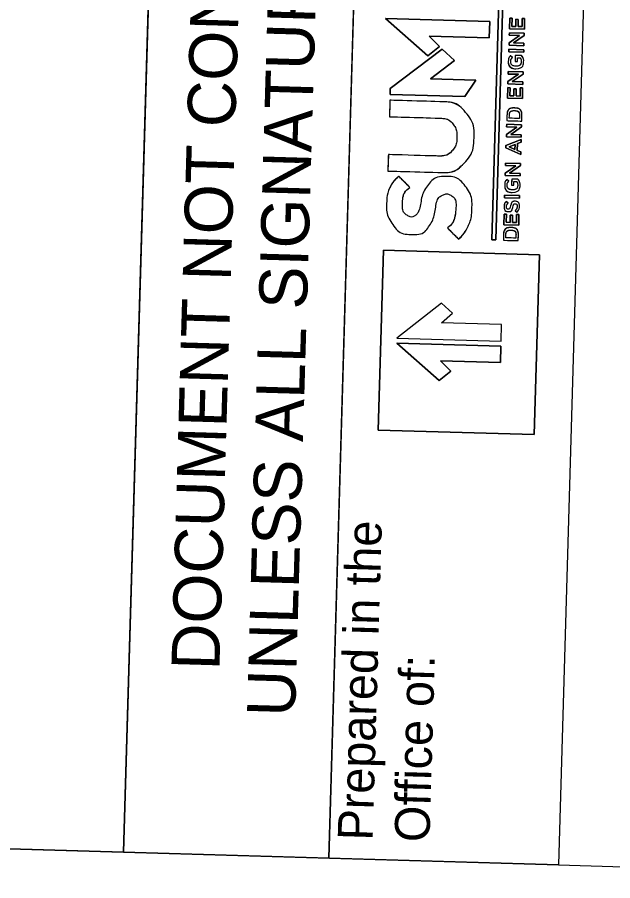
# Model space of a CAD drawing. Extents: x 2097000 to 2098148, y 684979 to 687012.
# Drawn here: x 2097192.5 to 2097260.6, y 686617.1 to 686715.9 of the extents above; entities that cross this region are included whole.
import ezdxf

# ---------------------------------------------------------------- set-up
doc = ezdxf.new("R2010")
doc.units = 0
for name, color, linetype in [('Sheet Block Title CELL', 7, 'Continuous'), ('Sheet Layout Plan Border', 7, 'Continuous'), ('Sheet Profile CELL', 7, 'Continuous'), ('Sheet Sticker Exception Certification CELL', 7, 'Continuous')]:
    doc.layers.add(name, color=color, linetype=linetype)

msp = doc.modelspace()

# ---------------------------------------------------------------- linework, layer by layer
at = {"layer": 'Sheet Block Title CELL'}
for p, q in [((2097249.112, 686711.281), (2097248.892, 686711.47)), ((2097249.497, 686709.984), (2097249.502, 686709.984)), ((2097249.506, 686710.284), (2097249.501, 686710.284)), ((2097249.367, 686705.496), (2097249.362, 686705.496)), ((2097249.358, 686705.195), (2097249.363, 686705.195)), ((2097237.381, 686696.412), (2097236.115, 686697.7)), ((2097248.701, 686697.137), (2097248.48, 686697.325)), ((2097249.086, 686695.839), (2097249.091, 686695.839)), ((2097249.095, 686696.139), (2097249.09, 686696.14)), ((2097248.616, 686694.646), (2097248.395, 686694.807)), ((2097249.423, 686694.825), (2097249.418, 686694.826)), ((2097249.439, 686694.538), (2097249.444, 686694.538)), ((2097248.627, 686693.937), (2097248.622, 686693.937)), ((2097248.641, 686693.65), (2097248.646, 686693.65)), ((2097249.413, 686693.735), (2097249.622, 686693.557)), ((2097241.682, 686691.784), (2097242.949, 686690.496)), ((2097248.969, 686691.824), (2097248.964, 686691.824)), ((2097248.96, 686691.523), (2097248.965, 686691.523))]:
    msp.add_line(p, q, dxfattribs=at)
for points in [[(2097228.129, 686619.71), (2097233.943, 686819.684), (2097260.188, 686818.921), (2097254.374, 686618.947)], [(2097233.761, 686668.67), (2097234.358, 686689.219), (2097252.194, 686688.7), (2097251.596, 686668.152)], [(2097235.893, 686679.192), (2097247.818, 686678.845), (2097247.873, 686680.724), (2097240.994, 686680.924), (2097242.26, 686682.051), (2097240.985, 686683.183)]]:
    msp.add_lwpolyline(points, close=True, dxfattribs=at)
for points in [[(2097248.533, 686735.929), (2097247.21, 686690.408), (2097246.758, 686690.422), (2097248.081, 686735.942), (2097248.533, 686735.929)], [(2097248.081, 686735.942), (2097246.758, 686690.422), (2097247.21, 686690.408), (2097248.533, 686735.929), (2097248.081, 686735.942)], [(2097234.598, 686715.748), (2097246.523, 686715.401), (2097246.468, 686713.523), (2097239.59, 686713.723), (2097240.787, 686712.523), (2097239.449, 686711.468), (2097234.598, 686715.748)], [(2097239.449, 686711.468), (2097240.787, 686712.523), (2097239.59, 686713.723), (2097246.468, 686713.523), (2097246.523, 686715.401), (2097234.598, 686715.748), (2097239.449, 686711.468)], [(2097248.779, 686714.553), (2097248.815, 686715.761), (2097249.082, 686715.753), (2097249.055, 686714.831), (2097249.497, 686714.819), (2097249.52, 686715.636), (2097249.788, 686715.628), (2097249.764, 686714.811), (2097250.22, 686714.797), (2097250.247, 686715.731), (2097250.514, 686715.724), (2097250.479, 686714.503), (2097248.779, 686714.553)], [(2097250.479, 686714.503), (2097250.514, 686715.724), (2097250.247, 686715.731), (2097250.22, 686714.797), (2097249.764, 686714.811), (2097249.788, 686715.628), (2097249.52, 686715.636), (2097249.497, 686714.819), (2097249.055, 686714.831), (2097249.082, 686715.753), (2097248.815, 686715.761), (2097248.779, 686714.553), (2097250.479, 686714.503)], [(2097248.725, 686712.667), (2097248.732, 686712.933), (2097249.933, 686713.772), (2097248.758, 686713.806), (2097248.766, 686714.088), (2097250.465, 686714.038), (2097250.458, 686713.798), (2097249.223, 686712.935), (2097250.432, 686712.9), (2097250.424, 686712.618), (2097248.725, 686712.667)], [(2097250.424, 686712.618), (2097250.432, 686712.9), (2097249.223, 686712.935), (2097250.458, 686713.798), (2097250.465, 686714.038), (2097248.766, 686714.088), (2097248.758, 686713.806), (2097249.933, 686713.772), (2097248.732, 686712.933), (2097248.725, 686712.667), (2097250.424, 686712.618)], [(2097235.141, 686707.717), (2097241.077, 686712.21), (2097242.502, 686710.937), (2097239.75, 686708.816), (2097244.914, 686708.665), (2097243.659, 686706.807), (2097235.121, 686707.055), (2097235.141, 686707.717)], [(2097235.121, 686707.055), (2097243.659, 686706.807), (2097244.914, 686708.665), (2097239.75, 686708.816), (2097242.502, 686710.937), (2097241.077, 686712.21), (2097235.141, 686707.717), (2097235.121, 686707.055)], [(2097248.703, 686711.922), (2097248.711, 686712.209), (2097250.411, 686712.159), (2097250.402, 686711.873), (2097248.703, 686711.922)], [(2097250.402, 686711.873), (2097250.411, 686712.159), (2097248.711, 686712.209), (2097248.703, 686711.922), (2097250.402, 686711.873)], [(2097250.156, 686711.491), (2097249.442, 686711.512), (2097249.422, 686710.818), (2097249.681, 686710.81), (2097249.694, 686711.227), (2097250.012, 686711.218)], [(2097248.596, 686708.242), (2097248.604, 686708.507), (2097249.804, 686709.346), (2097248.629, 686709.38), (2097248.637, 686709.662), (2097250.337, 686709.613), (2097250.33, 686709.373), (2097249.095, 686708.509), (2097250.304, 686708.474), (2097250.295, 686708.192), (2097248.596, 686708.242)], [(2097250.295, 686708.192), (2097250.304, 686708.474), (2097249.095, 686708.509), (2097250.33, 686709.373), (2097250.337, 686709.613), (2097248.637, 686709.662), (2097248.629, 686709.38), (2097249.804, 686709.346), (2097248.604, 686708.507), (2097248.596, 686708.242), (2097250.295, 686708.192)], [(2097248.549, 686706.612), (2097248.584, 686707.821), (2097248.851, 686707.813), (2097248.824, 686706.891), (2097249.266, 686706.878), (2097249.29, 686707.695), (2097249.557, 686707.687), (2097249.533, 686706.87), (2097249.989, 686706.857), (2097250.016, 686707.791), (2097250.283, 686707.783), (2097250.248, 686706.563), (2097248.549, 686706.612)], [(2097250.248, 686706.563), (2097250.283, 686707.783), (2097250.016, 686707.791), (2097249.989, 686706.857), (2097249.533, 686706.87), (2097249.557, 686707.687), (2097249.29, 686707.695), (2097249.266, 686706.878), (2097248.824, 686706.891), (2097248.851, 686707.813), (2097248.584, 686707.821), (2097248.549, 686706.612), (2097250.248, 686706.563)], [(2097241.253, 686706.202), (2097235.102, 686706.381), (2097235.047, 686704.502), (2097240.676, 686704.338)], [(2097248.492, 686704.654), (2097248.474, 686704.047), (2097250.173, 686703.997), (2097250.191, 686704.605)], [(2097249.919, 686704.613), (2097249.91, 686704.292), (2097248.754, 686704.325), (2097248.764, 686704.646)], [(2097248.421, 686702.208), (2097248.428, 686702.473), (2097249.629, 686703.312), (2097248.454, 686703.346), (2097248.462, 686703.628), (2097250.161, 686703.579), (2097250.154, 686703.339), (2097248.919, 686702.475), (2097250.128, 686702.44), (2097250.12, 686702.158), (2097248.421, 686702.208)], [(2097250.12, 686702.158), (2097250.128, 686702.44), (2097248.919, 686702.475), (2097250.154, 686703.339), (2097250.161, 686703.579), (2097248.462, 686703.628), (2097248.454, 686703.346), (2097249.629, 686703.312), (2097248.428, 686702.473), (2097248.421, 686702.208), (2097250.12, 686702.158)], [(2097248.372, 686700.946), (2097248.379, 686701.212), (2097250.112, 686701.879), (2097250.103, 686701.576), (2097249.688, 686701.423), (2097249.666, 686700.652), (2097250.071, 686700.473), (2097250.062, 686700.179), (2097248.372, 686700.946)], [(2097250.062, 686700.179), (2097250.071, 686700.473), (2097249.666, 686700.652), (2097249.688, 686701.423), (2097250.103, 686701.576), (2097250.112, 686701.879), (2097248.379, 686701.212), (2097248.372, 686700.946), (2097250.062, 686700.179)], [(2097249.42, 686701.326), (2097248.732, 686701.064), (2097249.404, 686700.765), (2097249.42, 686701.326)], [(2097249.404, 686700.765), (2097248.732, 686701.064), (2097249.42, 686701.326), (2097249.404, 686700.765)], [(2097240.55, 686700.003), (2097234.921, 686700.167), (2097234.867, 686698.288), (2097241.017, 686698.109)], [(2097248.292, 686697.784), (2097248.3, 686698.05), (2097249.5, 686698.889), (2097248.325, 686698.923), (2097248.333, 686699.205), (2097250.033, 686699.155), (2097250.026, 686698.915), (2097248.791, 686698.052), (2097250, 686698.017), (2097249.991, 686697.735), (2097248.292, 686697.784)], [(2097249.991, 686697.735), (2097250, 686698.017), (2097248.791, 686698.052), (2097250.026, 686698.915), (2097250.033, 686699.155), (2097248.333, 686699.205), (2097248.325, 686698.923), (2097249.5, 686698.889), (2097248.3, 686698.05), (2097248.292, 686697.784), (2097249.991, 686697.735)], [(2097249.744, 686697.346), (2097249.031, 686697.367), (2097249.011, 686696.673), (2097249.27, 686696.666), (2097249.282, 686697.083), (2097249.6, 686697.073)], [(2097248.218, 686695.238), (2097248.226, 686695.524), (2097249.926, 686695.475), (2097249.917, 686695.188), (2097248.218, 686695.238)], [(2097249.917, 686695.188), (2097249.926, 686695.475), (2097248.226, 686695.524), (2097248.218, 686695.238), (2097249.917, 686695.188)], [(2097248.128, 686692.148), (2097248.163, 686693.357), (2097248.43, 686693.349), (2097248.404, 686692.427), (2097248.845, 686692.414), (2097248.869, 686693.232), (2097249.136, 686693.224), (2097249.112, 686692.406), (2097249.569, 686692.393), (2097249.596, 686693.327), (2097249.863, 686693.319), (2097249.828, 686692.099), (2097248.128, 686692.148)], [(2097249.828, 686692.099), (2097249.863, 686693.319), (2097249.596, 686693.327), (2097249.569, 686692.393), (2097249.112, 686692.406), (2097249.136, 686693.224), (2097248.869, 686693.232), (2097248.845, 686692.414), (2097248.404, 686692.427), (2097248.43, 686693.349), (2097248.163, 686693.357), (2097248.128, 686692.148), (2097249.828, 686692.099)], [(2097248.094, 686690.982), (2097248.077, 686690.375), (2097249.776, 686690.325), (2097249.794, 686690.933)], [(2097249.522, 686690.941), (2097249.512, 686690.62), (2097248.357, 686690.653), (2097248.366, 686690.974)], [(2097234.358, 686689.219), (2097233.761, 686668.67), (2097251.596, 686668.152), (2097252.194, 686688.7), (2097234.358, 686689.219)], [(2097235.893, 686679.192), (2097247.818, 686678.845), (2097247.873, 686680.724), (2097240.994, 686680.924), (2097242.26, 686682.051), (2097240.985, 686683.183), (2097235.893, 686679.192)], [(2097235.876, 686678.614), (2097247.801, 686678.267), (2097247.747, 686676.388), (2097240.868, 686676.588), (2097242.066, 686675.389), (2097240.727, 686674.333), (2097235.876, 686678.614)], [(2097240.727, 686674.333), (2097242.066, 686675.389), (2097240.868, 686676.588), (2097247.747, 686676.388), (2097247.801, 686678.267), (2097235.876, 686678.614), (2097240.727, 686674.333)]]:
    msp.add_lwpolyline(points, dxfattribs=at)
for points, degree in [([(2097249.502, 686709.984), (2097249.502, 686709.984), (2097249.497, 686709.984), (2097249.497, 686709.984), (2097249.021, 686709.998), (2097248.628, 686710.359), (2097248.643, 686710.85), (2097248.651, 686711.134), (2097248.739, 686711.306), (2097248.892, 686711.47), (2097248.892, 686711.47), (2097249.112, 686711.281), (2097249.112, 686711.281), (2097248.997, 686711.159), (2097248.923, 686711.038), (2097248.917, 686710.83), (2097248.908, 686710.53), (2097249.176, 686710.294), (2097249.501, 686710.284), (2097249.501, 686710.284), (2097249.506, 686710.284), (2097249.506, 686710.284), (2097249.855, 686710.274), (2097250.119, 686710.488), (2097250.129, 686710.821), (2097250.133, 686710.975), (2097250.086, 686711.116), (2097250.012, 686711.218), (2097250.012, 686711.218), (2097249.694, 686711.227), (2097249.694, 686711.227), (2097249.694, 686711.227), (2097249.681, 686710.81), (2097249.681, 686710.81), (2097249.681, 686710.81), (2097249.422, 686710.818), (2097249.422, 686710.818), (2097249.422, 686710.818), (2097249.442, 686711.512), (2097249.442, 686711.512), (2097249.442, 686711.512), (2097250.156, 686711.491), (2097250.156, 686711.491), (2097250.294, 686711.327), (2097250.409, 686711.092), (2097250.4, 686710.804), (2097250.386, 686710.294), (2097249.997, 686709.969), (2097249.502, 686709.984)], 3), ([(2097248.892, 686711.47), (2097248.739, 686711.306), (2097248.651, 686711.134), (2097248.643, 686710.85), (2097248.628, 686710.359), (2097249.021, 686709.998), (2097249.497, 686709.984)], 3), ([(2097249.502, 686709.984), (2097249.997, 686709.969), (2097250.386, 686710.294), (2097250.4, 686710.804), (2097250.409, 686711.092), (2097250.294, 686711.327), (2097250.156, 686711.491)], 3), ([(2097249.501, 686710.284), (2097249.176, 686710.294), (2097248.908, 686710.53), (2097248.917, 686710.83), (2097248.923, 686711.038), (2097248.997, 686711.159), (2097249.112, 686711.281)], 3), ([(2097250.012, 686711.218), (2097250.086, 686711.116), (2097250.133, 686710.975), (2097250.129, 686710.821), (2097250.119, 686710.488), (2097249.855, 686710.274), (2097249.506, 686710.284)], 3), ([(2097234.921, 686700.167), (2097234.921, 686700.167), (2097240.55, 686700.003), (2097240.55, 686700.003), (2097241.29, 686699.982), (2097241.838, 686700.179), (2097242.198, 686700.585), (2097242.558, 686700.992), (2097242.747, 686701.51), (2097242.765, 686702.135), (2097242.783, 686702.76), (2097242.624, 686703.263), (2097242.288, 686703.689), (2097241.953, 686704.116), (2097241.416, 686704.317), (2097240.676, 686704.338), (2097240.676, 686704.338), (2097235.047, 686704.502), (2097235.047, 686704.502), (2097235.047, 686704.502), (2097235.102, 686706.381), (2097235.102, 686706.381), (2097235.102, 686706.381), (2097241.253, 686706.202), (2097241.253, 686706.202), (2097242.252, 686706.173), (2097243.088, 686705.786), (2097243.761, 686704.994), (2097244.434, 686704.203), (2097244.754, 686703.236), (2097244.72, 686702.069), (2097244.686, 686700.902), (2097244.31, 686699.943), (2097243.592, 686699.192), (2097242.875, 686698.441), (2097242.017, 686698.08), (2097241.017, 686698.109), (2097241.017, 686698.109), (2097234.867, 686698.288), (2097234.867, 686698.288), (2097234.867, 686698.288), (2097234.921, 686700.167), (2097234.921, 686700.167)], 3), ([(2097241.017, 686698.109), (2097242.017, 686698.08), (2097242.875, 686698.441), (2097243.592, 686699.192), (2097244.31, 686699.943), (2097244.686, 686700.902), (2097244.72, 686702.069), (2097244.754, 686703.236), (2097244.434, 686704.203), (2097243.761, 686704.994), (2097243.088, 686705.786), (2097242.252, 686706.173), (2097241.253, 686706.202)], 3), ([(2097248.474, 686704.047), (2097248.474, 686704.047), (2097248.492, 686704.654), (2097248.492, 686704.654), (2097248.507, 686705.167), (2097248.883, 686705.51), (2097249.362, 686705.496), (2097249.362, 686705.496), (2097249.367, 686705.496), (2097249.367, 686705.496), (2097249.845, 686705.482), (2097250.206, 686705.117), (2097250.191, 686704.605), (2097250.191, 686704.605), (2097250.173, 686703.997), (2097250.173, 686703.997), (2097250.173, 686703.997), (2097248.474, 686704.047), (2097248.474, 686704.047)], 3), ([(2097249.362, 686705.496), (2097248.883, 686705.51), (2097248.507, 686705.167), (2097248.492, 686704.654)], 2), ([(2097250.191, 686704.605), (2097250.206, 686705.117), (2097249.845, 686705.482), (2097249.367, 686705.496)], 2), ([(2097248.754, 686704.325), (2097248.754, 686704.325), (2097249.91, 686704.292), (2097249.91, 686704.292), (2097249.91, 686704.292), (2097249.919, 686704.613), (2097249.919, 686704.613), (2097249.929, 686704.955), (2097249.695, 686705.186), (2097249.363, 686705.195), (2097249.363, 686705.195), (2097249.358, 686705.195), (2097249.358, 686705.195), (2097249.025, 686705.205), (2097248.774, 686704.989), (2097248.764, 686704.646), (2097248.764, 686704.646), (2097248.754, 686704.325), (2097248.754, 686704.325)], 3), ([(2097248.764, 686704.646), (2097248.774, 686704.989), (2097249.025, 686705.205), (2097249.358, 686705.195)], 2), ([(2097249.363, 686705.195), (2097249.695, 686705.186), (2097249.929, 686704.955), (2097249.919, 686704.613)], 2), ([(2097240.676, 686704.338), (2097241.416, 686704.317), (2097241.953, 686704.116), (2097242.288, 686703.689), (2097242.624, 686703.263), (2097242.783, 686702.76), (2097242.765, 686702.135), (2097242.747, 686701.51), (2097242.558, 686700.992), (2097242.198, 686700.585), (2097241.838, 686700.179), (2097241.29, 686699.982), (2097240.55, 686700.003)], 3), ([(2097235.098, 686696.385), (2097235.329, 686696.858), (2097235.668, 686697.296), (2097236.115, 686697.7), (2097236.115, 686697.7), (2097237.381, 686696.412), (2097237.381, 686696.412), (2097236.848, 686696.011), (2097236.57, 686695.436), (2097236.548, 686694.685), (2097236.527, 686693.935), (2097236.697, 686693.451), (2097237.061, 686693.231), (2097237.424, 686693.013), (2097237.739, 686693.004), (2097238.005, 686693.204), (2097238.272, 686693.405), (2097238.482, 686693.878), (2097238.634, 686694.624), (2097238.743, 686695.413), (2097239.036, 686696.125), (2097239.511, 686696.757), (2097239.986, 686697.39), (2097240.723, 686697.691), (2097241.722, 686697.662), (2097242.504, 686697.639), (2097243.167, 686697.275), (2097243.712, 686696.569), (2097244.257, 686695.864), (2097244.516, 686695.052), (2097244.489, 686694.135), (2097244.464, 686693.264), (2097244.312, 686692.541), (2097244.035, 686691.965), (2097243.757, 686691.389), (2097243.395, 686690.9), (2097242.949, 686690.496), (2097242.949, 686690.496), (2097241.682, 686691.784), (2097241.682, 686691.784), (2097242.215, 686692.185), (2097242.54, 686692.885), (2097242.656, 686693.882), (2097242.68, 686694.716), (2097242.51, 686695.241), (2097242.147, 686695.458), (2097241.784, 686695.675), (2097241.415, 686695.685), (2097241.039, 686695.49), (2097240.664, 686695.295), (2097240.421, 686694.781), (2097240.31, 686693.95), (2097240.201, 686693.203), (2097239.942, 686692.523), (2097239.533, 686691.909), (2097239.124, 686691.295), (2097238.442, 686691.002), (2097237.486, 686691.03), (2097236.621, 686691.055), (2097235.938, 686691.43), (2097235.435, 686692.156), (2097234.932, 686692.882), (2097234.692, 686693.619), (2097234.713, 686694.369), (2097234.739, 686695.24), (2097234.866, 686695.912), (2097235.098, 686696.385)], 3), ([(2097236.115, 686697.7), (2097235.668, 686697.296), (2097235.329, 686696.858), (2097235.098, 686696.385)], 2), ([(2097242.949, 686690.496), (2097243.395, 686690.9), (2097243.757, 686691.389), (2097244.035, 686691.965), (2097244.312, 686692.541), (2097244.464, 686693.264), (2097244.489, 686694.135), (2097244.516, 686695.052), (2097244.257, 686695.864), (2097243.712, 686696.569), (2097243.167, 686697.275), (2097242.504, 686697.639), (2097241.722, 686697.662), (2097240.723, 686697.691), (2097239.986, 686697.39), (2097239.511, 686696.757), (2097239.036, 686696.125), (2097238.743, 686695.413), (2097238.634, 686694.624), (2097238.482, 686693.878), (2097238.272, 686693.405), (2097238.005, 686693.204), (2097237.739, 686693.004), (2097237.424, 686693.013), (2097237.061, 686693.231), (2097236.697, 686693.451), (2097236.527, 686693.935), (2097236.548, 686694.685), (2097236.57, 686695.436), (2097236.848, 686696.011), (2097237.381, 686696.412)], 3), ([(2097249.091, 686695.839), (2097249.091, 686695.839), (2097249.086, 686695.839), (2097249.086, 686695.839), (2097248.61, 686695.853), (2097248.217, 686696.214), (2097248.231, 686696.705), (2097248.24, 686696.989), (2097248.327, 686697.161), (2097248.48, 686697.325), (2097248.48, 686697.325), (2097248.701, 686697.137), (2097248.701, 686697.137), (2097248.585, 686697.014), (2097248.511, 686696.893), (2097248.505, 686696.686), (2097248.497, 686696.385), (2097248.764, 686696.149), (2097249.09, 686696.14), (2097249.09, 686696.14), (2097249.095, 686696.139), (2097249.095, 686696.139), (2097249.444, 686696.129), (2097249.708, 686696.343), (2097249.718, 686696.676), (2097249.722, 686696.83), (2097249.675, 686696.971), (2097249.6, 686697.073), (2097249.6, 686697.073), (2097249.282, 686697.083), (2097249.282, 686697.083), (2097249.282, 686697.083), (2097249.27, 686696.666), (2097249.27, 686696.666), (2097249.27, 686696.666), (2097249.011, 686696.673), (2097249.011, 686696.673), (2097249.011, 686696.673), (2097249.031, 686697.367), (2097249.031, 686697.367), (2097249.031, 686697.367), (2097249.744, 686697.346), (2097249.744, 686697.346), (2097249.883, 686697.182), (2097249.998, 686696.947), (2097249.989, 686696.659), (2097249.974, 686696.149), (2097249.586, 686695.825), (2097249.091, 686695.839)], 3), ([(2097248.48, 686697.325), (2097248.327, 686697.161), (2097248.24, 686696.989), (2097248.231, 686696.705), (2097248.217, 686696.214), (2097248.61, 686695.853), (2097249.086, 686695.839)], 3), ([(2097249.09, 686696.14), (2097248.764, 686696.149), (2097248.497, 686696.385), (2097248.505, 686696.686), (2097248.511, 686696.893), (2097248.585, 686697.014), (2097248.701, 686697.137)], 3), ([(2097249.091, 686695.839), (2097249.586, 686695.825), (2097249.974, 686696.149), (2097249.989, 686696.659), (2097249.998, 686696.947), (2097249.883, 686697.182), (2097249.744, 686697.346)], 3), ([(2097249.6, 686697.073), (2097249.675, 686696.971), (2097249.722, 686696.83), (2097249.718, 686696.676), (2097249.708, 686696.343), (2097249.444, 686696.129), (2097249.095, 686696.139)], 3), ([(2097235.098, 686696.385), (2097234.866, 686695.912), (2097234.739, 686695.24), (2097234.713, 686694.369), (2097234.692, 686693.619), (2097234.932, 686692.882), (2097235.435, 686692.156), (2097235.938, 686691.43), (2097236.621, 686691.055), (2097237.486, 686691.03), (2097238.442, 686691.002), (2097239.124, 686691.295), (2097239.533, 686691.909), (2097239.942, 686692.523), (2097240.201, 686693.203), (2097240.31, 686693.95), (2097240.421, 686694.781), (2097240.664, 686695.295), (2097241.039, 686695.49), (2097241.415, 686695.685), (2097241.784, 686695.675), (2097242.147, 686695.458), (2097242.51, 686695.241), (2097242.68, 686694.716), (2097242.656, 686693.882), (2097242.54, 686692.885), (2097242.215, 686692.185), (2097241.682, 686691.784)], 3), ([(2097249.622, 686693.557), (2097249.622, 686693.557), (2097249.413, 686693.735), (2097249.413, 686693.735), (2097249.559, 686693.887), (2097249.644, 686694.043), (2097249.649, 686694.243), (2097249.655, 686694.42), (2097249.57, 686694.535), (2097249.444, 686694.538), (2097249.444, 686694.538), (2097249.439, 686694.538), (2097249.439, 686694.538), (2097249.318, 686694.542), (2097249.25, 686694.479), (2097249.169, 686694.178), (2097249.071, 686693.834), (2097248.959, 686693.641), (2097248.646, 686693.65), (2097248.646, 686693.65), (2097248.641, 686693.65), (2097248.641, 686693.65), (2097248.349, 686693.659), (2097248.155, 686693.897), (2097248.164, 686694.221), (2097248.171, 686694.459), (2097248.252, 686694.645), (2097248.395, 686694.807), (2097248.395, 686694.807), (2097248.616, 686694.646), (2097248.616, 686694.646), (2097248.498, 686694.503), (2097248.433, 686694.358), (2097248.429, 686694.209), (2097248.424, 686694.041), (2097248.511, 686693.941), (2097248.622, 686693.937), (2097248.622, 686693.937), (2097248.627, 686693.937), (2097248.627, 686693.937), (2097248.758, 686693.933), (2097248.819, 686694.006), (2097248.906, 686694.318), (2097249.003, 686694.66), (2097249.137, 686694.834), (2097249.418, 686694.826), (2097249.418, 686694.826), (2097249.423, 686694.825), (2097249.423, 686694.825), (2097249.741, 686694.816), (2097249.924, 686694.571), (2097249.914, 686694.229), (2097249.907, 686693.979), (2097249.81, 686693.747), (2097249.622, 686693.557)], 3), ([(2097248.395, 686694.807), (2097248.252, 686694.645), (2097248.171, 686694.459), (2097248.164, 686694.221), (2097248.155, 686693.897), (2097248.349, 686693.659), (2097248.641, 686693.65)], 3), ([(2097248.622, 686693.937), (2097248.511, 686693.941), (2097248.424, 686694.041), (2097248.429, 686694.209), (2097248.433, 686694.358), (2097248.498, 686694.503), (2097248.616, 686694.646)], 3), ([(2097249.418, 686694.826), (2097249.137, 686694.834), (2097249.003, 686694.66), (2097248.906, 686694.318), (2097248.819, 686694.006), (2097248.758, 686693.933), (2097248.627, 686693.937)], 3), ([(2097248.646, 686693.65), (2097248.959, 686693.641), (2097249.071, 686693.834), (2097249.169, 686694.178), (2097249.25, 686694.479), (2097249.318, 686694.542), (2097249.439, 686694.538)], 3), ([(2097249.444, 686694.538), (2097249.57, 686694.535), (2097249.655, 686694.42), (2097249.649, 686694.243), (2097249.644, 686694.043), (2097249.559, 686693.887), (2097249.413, 686693.735)], 3), ([(2097249.622, 686693.557), (2097249.81, 686693.747), (2097249.907, 686693.979), (2097249.914, 686694.229), (2097249.924, 686694.571), (2097249.741, 686694.816), (2097249.423, 686694.825)], 3), ([(2097248.077, 686690.375), (2097248.077, 686690.375), (2097248.094, 686690.982), (2097248.094, 686690.982), (2097248.109, 686691.495), (2097248.486, 686691.838), (2097248.964, 686691.824), (2097248.964, 686691.824), (2097248.969, 686691.824), (2097248.969, 686691.824), (2097249.447, 686691.81), (2097249.809, 686691.445), (2097249.794, 686690.933), (2097249.794, 686690.933), (2097249.776, 686690.325), (2097249.776, 686690.325), (2097249.776, 686690.325), (2097248.077, 686690.375), (2097248.077, 686690.375)], 3), ([(2097248.964, 686691.824), (2097248.486, 686691.838), (2097248.109, 686691.495), (2097248.094, 686690.982)], 2), ([(2097249.794, 686690.933), (2097249.809, 686691.445), (2097249.447, 686691.81), (2097248.969, 686691.824)], 2), ([(2097248.357, 686690.653), (2097248.357, 686690.653), (2097249.512, 686690.62), (2097249.512, 686690.62), (2097249.512, 686690.62), (2097249.522, 686690.941), (2097249.522, 686690.941), (2097249.532, 686691.283), (2097249.298, 686691.514), (2097248.965, 686691.523), (2097248.965, 686691.523), (2097248.96, 686691.523), (2097248.96, 686691.523), (2097248.628, 686691.533), (2097248.376, 686691.317), (2097248.366, 686690.974), (2097248.366, 686690.974), (2097248.357, 686690.653), (2097248.357, 686690.653)], 3), ([(2097248.366, 686690.974), (2097248.376, 686691.317), (2097248.628, 686691.533), (2097248.96, 686691.523)], 2), ([(2097248.965, 686691.523), (2097249.298, 686691.514), (2097249.532, 686691.283), (2097249.522, 686690.941)], 2)]:
    msp.add_open_spline(points, degree=degree, dxfattribs=at)
at = {"layer": 'Sheet Layout Plan Border'}
msp.add_lwpolyline([(2098090.846, 685704.417), (2097236.932, 685318.955), (2097029.373, 685324.989), (2097067.147, 686624.39), (2097254.374, 686618.947), (2097261.847, 686618.73), (2097260.988, 686589.187), (2097439.335, 686584.003), (2097443.487, 686726.823), (2098119.997, 686707.157)], close=True, dxfattribs=at)
at = {"layer": 'Sheet Profile CELL'}
msp.add_lwpolyline([(2097092.187, 686623.662), (2097095.094, 686723.67), (2097207.547, 686720.401), (2097204.639, 686620.393)], close=True, dxfattribs=at)
at = {"layer": 'Sheet Sticker Exception Certification CELL'}
for p, q in [((2097204.639, 686620.393), (2097210.452, 686820.346)), ((2097233.942, 686819.663), (2097228.129, 686619.71)), ((2097228.129, 686619.71), (2097204.639, 686620.393))]:
    msp.add_line(p, q, dxfattribs=at)

# ---------------------------------------------------------------- texts
at = {"layer": 'Sheet Block Title CELL'}
for s, height, p in [('Prepared in the ', 4.00116, (2097233.122, 686621.688)), ('Office of:', 4.0012, (2097239.622, 686621.499))]:
    msp.add_text(s, height=height, rotation=88.33483, dxfattribs=at).set_placement(p)
at = {"layer": 'Sheet Sticker Exception Certification CELL'}
for s, p in [('UNLESS ALL SIGNATURES COMPLETED', (2097224.241, 686635.83)), ('DOCUMENT NOT CONSIDERED FINAL', (2097215.593, 686641.154))]:
    msp.add_text(s, height=5.5, rotation=88.33483, dxfattribs=at).set_placement(p)

doc.saveas('drawing.dxf')
